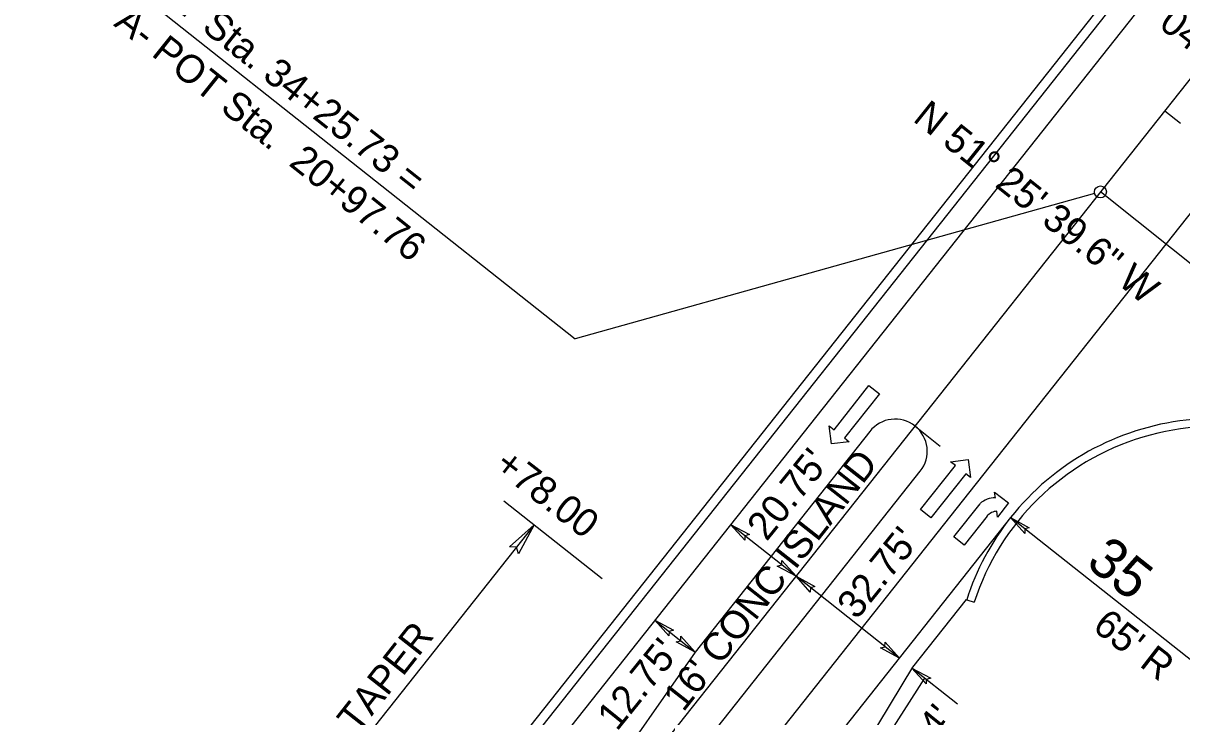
# Model space of a CAD drawing. Extents: x 1778969 to 1790720, y 807089 to 817794.
# Drawn here: x 1781916 to 1782204, y 813729.3 to 813901.8 of the extents above; entities that cross this region are included whole.
import ezdxf

# ---------------------------------------------------------------- set-up
doc = ezdxf.new("R2010")
doc.units = 0
for name, color, linetype in [('Prop Conc 2ft 6in Curb and Gutter', 7, 'Continuous'), ('Prop Conc 5in Monolithic Surface Mount Island', 7, 'Continuous'), ('Prop Conc Shoulder Berm Gutter', 7, 'Continuous'), ('Prop Dimension', 7, 'Continuous'), ('Prop Dimension Text', 7, 'Continuous'), ('Prop EOT', 7, 'Continuous'), ('Prop Guardrail', 7, 'Continuous'), ('Prop Horizontal Alignment', 7, 'Continuous'), ('Prop Horizontal Alignment Direction Label', 7, 'Continuous'), ('Prop Horizontal Alignment Station Label', 7, 'Continuous'), ('Prop Horizontal Alignment Tick Label', 7, 'Continuous'), ('Prop Horizontal Alignment Tick Large', 7, 'Continuous'), ('Prop Horizontal Alignment Tick Small', 7, 'Continuous'), ('Prop Lane Arrow CELL', 7, 'Continuous'), ('Prop Lane Lines', 7, 'Continuous'), ('Prop Paved Shoulder', 7, 'Continuous'), ('Prop Terminator CELL', 7, 'Continuous'), ('Scratch_Level_2', 7, 'Continuous'), ('Scratch_Level_7', 7, 'Continuous'), ('Scratch_Level_8', 7, 'Continuous')]:
    doc.layers.add(name, color=color, linetype=linetype)

msp = doc.modelspace()

# ---------------------------------------------------------------- linework, layer by layer
at = {"layer": 'Prop Conc 2ft 6in Curb and Gutter'}
msp.add_line((1782150.56, 813758.42), (1782152.46, 813757.81), dxfattribs=at)
for radius, start in [(63, 51.2517), (65, 141.6309)]:
    msp.add_arc((1782212.43, 813738.51), radius, start, 162.1578, dxfattribs=at)
at = {"layer": 'Prop Conc 5in Monolithic Surface Mount Island'}
for p, q in [((1782126.48, 813800.31), (1782083.03, 813745.43)), ((1782126.48, 813800.31), (1782083.03, 813745.43)), ((1781549.8, 813046.14), (1782139.02, 813790.38)), ((1781549.8, 813046.14), (1782139.02, 813790.38)), ((1782083.03, 813745.43), (1781968.29, 813581.17)), ((1782083.03, 813745.43), (1781968.29, 813581.17))]:
    msp.add_line(p, q, dxfattribs=at)
msp.add_arc((1782132.75, 813795.34), 8, 321.6309, 141.6309, dxfattribs=at)
msp.add_arc((1782132.75, 813795.34), 8, 321.6309, 141.6309, dxfattribs=at)
at = {"layer": 'Prop Conc Shoulder Berm Gutter'}
msp.add_line((1782463.39, 814255.53), (1782011.16, 813684.33), dxfattribs=at)
at = {"layer": 'Prop Dimension'}
for p, q in [((1782035.5, 813783.05), (1782059.91, 813763.73)), ((1782043.04, 813777.09), (1781918.89, 813620.28)), ((1782108.14, 813764.26), (1782091.87, 813777.14)), ((1782212.43, 813738.51), (1782161.47, 813778.86)), ((1782133.82, 813743.93), (1782108.14, 813764.26)), ((1782073.09, 813753.3), (1782083.03, 813745.43)), ((1782148.26, 813732.49), (1782136.95, 813741.45))]:
    msp.add_line(p, q, dxfattribs=at)
at = {"layer": 'Prop EOT'}
for p, q in [((1782467.83, 814252.01), (1781527.26, 813063.99)), ((1782161.47, 813778.86), (1782107.53, 813710.72))]:
    msp.add_line(p, q, dxfattribs=at)
msp.add_arc((1782212.43, 813738.51), 65, 51.2517, 141.6309, dxfattribs=at)
for points in [[(1781463.3, 813949.03), (1781464.17, 813947.59), (1781465.05, 813946.15), (1781465.92, 813944.71), (1781474.8, 813929.99), (1781483.67, 813915.26), (1781492.5, 813900.51), (1781500.58, 813887.01), (1781508.59, 813873.47), (1781516.69, 813859.98), (1781525.21, 813845.83), (1781533.74, 813831.69), (1781542.26, 813817.54), (1781551.3, 813802.52), (1781560.33, 813787.49), (1781569.37, 813772.46), (1781578.14, 813757.89), (1781587.14, 813743.46), (1781595.91, 813728.89), (1781604.33, 813714.9), (1781612.49, 813700.76), (1781620.9, 813686.76), (1781629.44, 813672.57), (1781637.98, 813658.38), (1781646.54, 813644.19), (1781655.1, 813630), (1781663.72, 813615.84), (1781672.26, 813601.63), (1781680.69, 813587.61), (1781689, 813573.52), (1781697.41, 813559.48), (1781705.95, 813545.23), (1781714.52, 813530.99), (1781723.07, 813516.73), (1781731.64, 813502.44), (1781740.12, 813488.1), (1781748.7, 813473.81), (1781757.55, 813459.07), (1781766.63, 813444.47), (1781775.52, 813429.74), (1781784.14, 813415.46), (1781792.67, 813401.11), (1781801.32, 813386.83), (1781809.96, 813372.55), (1781818.65, 813358.29), (1781827.3, 813344.02), (1781835.99, 813329.66), (1781844.67, 813315.3), (1781853.35, 813300.93), (1781861.54, 813287.37), (1781869.6, 813273.73), (1781877.8, 813260.18), (1781886.68, 813245.53), (1781895.77, 813231.01), (1781904.68, 813216.38), (1781913.11, 813202.51), (1781921.54, 813188.63), (1781929.97, 813174.75), (1781938.85, 813160.12), (1781947.7, 813145.46), (1781956.59, 813130.83), (1781964.95, 813117.07), (1781973.52, 813103.43), (1781982.19, 813089.85), (1781991.2, 813075.72), (1782000.27, 813061.63), (1782009.36, 813047.54), (1782018.57, 813033.28), (1782027.8, 813019.03), (1782037.07, 813004.8), (1782046.22, 812990.76), (1782055.4, 812976.74), (1782064.84, 812962.89), (1782074.16, 812949.23), (1782083.5, 812935.58), (1782092.82, 812921.91), (1782102.18, 812908.19), (1782111.54, 812894.47), (1782120.9, 812880.75), (1782130.3, 812866.98), (1782139.85, 812853.32), (1782149.42, 812839.67), (1782158.88, 812826.17), (1782168.45, 812812.74), (1782178.15, 812799.41), (1782187.7, 812786.29), (1782197.57, 812773.41), (1782207.08, 812760.26), (1782216.45, 812747.28), (1782225.83, 812734.3), (1782235.2, 812721.32)], [(1781718, 813799.07), (1781725.25, 813787.64), (1781732.32, 813776.09), (1781739.53, 813764.62), (1781748.41, 813750.49), (1781757.28, 813736.36), (1781766.17, 813722.23), (1781775.05, 813708.11), (1781784.04, 813694.06), (1781792.91, 813679.93), (1781801.78, 813665.79), (1781810.64, 813651.64), (1781819.51, 813637.51), (1781828.35, 813623.41), (1781837.2, 813609.31), (1781846.04, 813595.21), (1781854.91, 813581.09), (1781863.8, 813566.98), (1781872.77, 813552.92), (1781881.67, 813538.97), (1781890.62, 813525.06), (1781899.56, 813511.14), (1781909.02, 813496.43), (1781918.41, 813481.67), (1781927.98, 813467.03), (1781936.67, 813453.72), (1781945.44, 813440.46), (1781954.18, 813427.18), (1781963.4, 813413.19), (1781972.62, 813399.19), (1781981.85, 813385.2), (1781991.28, 813370.91), (1782000.79, 813356.66), (1782010.37, 813342.46), (1782019.44, 813329.02), (1782028.6, 813315.64), (1782037.78, 813302.29), (1782047.33, 813288.38), (1782056.88, 813274.48), (1782066.55, 813260.66), (1782076.08, 813247.05), (1782085.65, 813233.46), (1782095.22, 813219.88), (1782104.86, 813206.2), (1782114.49, 813192.52), (1782124.19, 813178.89), (1782133.79, 813165.38), (1782143.47, 813151.93), (1782153.2, 813138.53), (1782163.03, 813124.99), (1782172.87, 813111.45), (1782182.7, 813097.92), (1782192.49, 813084.44), (1782202.28, 813070.96), (1782212.1, 813057.5), (1782222.19, 813043.65), (1782232.6, 813030.04), (1782242.95, 813016.38), (1782253.03, 813003.08), (1782263.13, 812989.8), (1782273.21, 812976.5), (1782283.25, 812963.25), (1782293.24, 812949.97), (1782303.28, 812936.71), (1782313.15, 812923.68), (1782323.08, 812910.68), (1782333.22, 812897.85), (1782343.55, 812884.78), (1782353.98, 812871.79), (1782364.43, 812858.81), (1782374.92, 812845.79), (1782385.44, 812832.79), (1782395.93, 812819.76), (1782406.63, 812806.47), (1782417.16, 812793.03), (1782427.96, 812779.81), (1782438.52, 812766.89), (1782449.19, 812754.07), (1782459.83, 812741.21), (1782470.24, 812728.63), (1782480.58, 812715.98), (1782491.09, 812703.48), (1782501.82, 812690.7), (1782512.68, 812678.03), (1782523.5, 812665.33), (1782534.27, 812652.67), (1782545.05, 812640.01), (1782555.83, 812627.36), (1782566.67, 812614.64), (1782577.52, 812601.95), (1782588.45, 812589.31), (1782599.39, 812576.64), (1782610.53, 812564.14), (1782621.67, 812551.65), (1782632.74, 812539.22), (1782643.82, 812526.79), (1782655, 812514.46), (1782666.21, 812502.08), (1782677.45, 812489.72), (1782688.69, 812477.37), (1782699.92, 812465.03), (1782711.15, 812452.71), (1782722.41, 812440.4), (1782733.64, 812428.12), (1782744.98, 812415.94), (1782756.33, 812403.76), (1782767.99, 812391.23), (1782779.7, 812378.74), (1782791.5, 812366.34), (1782803.09, 812354.16), (1782814.85, 812342.15), (1782826.46, 812330), (1782838.01, 812317.9), (1782849.46, 812305.7), (1782861.02, 812293.59), (1782872.17, 812281.92), (1782883.35, 812270.25), (1782894.68, 812258.74), (1782906.41, 812246.83), (1782918.19, 812234.96), (1782929.97, 812223.1), (1782941.62, 812211.36), (1782953.24, 812199.57), (1782964.97, 812187.91), (1782968.29, 812184.62), (1782971.62, 812181.35), (1782974.95, 812178.08)]]:
    msp.add_open_spline(points, degree=3, dxfattribs=at)
at = {"layer": 'Prop Guardrail'}
msp.add_line((1782461.56, 814256.98), (1782009.33, 813685.78), dxfattribs=at)
at = {"layer": 'Prop Horizontal Alignment'}
for p, q in [((1782484.1, 814239.13), (1781543.53, 813051.11)), ((1782246.76, 813809.64), (1782183.81, 813859.84))]:
    msp.add_line(p, q, dxfattribs=at)
at = {"layer": 'Prop Horizontal Alignment Station Label'}
for p in [(1781926.47, 813923.69), (1782182.37, 813859.44)]:
    msp.add_line(p, (1782053.22, 813823.34), dxfattribs=at)
msp.add_circle((1782183.81, 813859.84), 1.5, dxfattribs=at)
at = {"layer": 'Prop Horizontal Alignment Tick Large'}
msp.add_line((1782137.72, 813801.62), (1782143.99, 813796.65), dxfattribs=at)
at = {"layer": 'Prop Horizontal Alignment Tick Small'}
msp.add_line((1782199.79, 813880.02), (1782203.71, 813876.91), dxfattribs=at)
at = {"layer": 'Prop Lane Arrow CELL'}
for p, q in [((1782117.58, 813800.71), (1782126.27, 813811.68)), ((1782126.27, 813811.68), (1782128.85, 813809.64)), ((1782128.85, 813809.64), (1782120.16, 813798.66)), ((1782116.95, 813797.18), (1782116.4, 813801.64)), ((1782116.4, 813801.64), (1782117.58, 813800.71)), ((1782121.34, 813797.73), (1782116.95, 813797.18)), ((1782120.16, 813798.66), (1782121.34, 813797.73)), ((1782139.06, 813780.84), (1782147.75, 813791.82)), ((1782146.57, 813792.75), (1782150.96, 813793.29)), ((1782147.75, 813791.82), (1782146.57, 813792.75)), ((1782150.96, 813793.29), (1782151.51, 813788.84)), ((1782150.33, 813789.77), (1782141.64, 813778.79)), ((1782151.51, 813788.84), (1782150.33, 813789.77)), ((1782157.69, 813783.73), (1782157.51, 813785.2)), ((1782157.51, 813785.2), (1782160.99, 813782.51)), ((1782160.99, 813782.51), (1782158.24, 813778.95)), ((1782141.64, 813778.79), (1782139.06, 813780.84)), ((1782147.35, 813774.05), (1782153.9, 813782.32)), ((1782158.24, 813778.95), (1782158.07, 813780.42)), ((1782155.62, 813779.18), (1782149.94, 813772)), ((1782149.94, 813772), (1782147.35, 813774.05))]:
    msp.add_line(p, q, dxfattribs=at)
for centre, radius, start, end in [((1782157.46, 813778.49), 5.25, 87.6432, 132.9549), ((1782158.18, 813777.16), 3.28, 91.9728, 141.6309)]:
    msp.add_arc(centre, radius, start, end, dxfattribs=at)
at = {"layer": 'Prop Lane Lines'}
msp.add_line((1782152.88, 813787.34), (1782077.29, 813691.86), dxfattribs=at)
at = {"layer": 'Prop Paved Shoulder'}
for p, q in [((1782150.46, 813758.5), (1782137.1, 813741.63)), ((1782137.1, 813741.63), (1782117.66, 813709.59))]:
    msp.add_line(p, q, dxfattribs=at)
at = {"layer": 'Prop Terminator CELL'}
for points in [[(1782036.92, 813771.6), (1782043.04, 813777.09), (1782039.11, 813769.81), (1782038.63, 813771.51)], [(1782095.38, 813773.22), (1782091.87, 813777.14), (1782096.53, 813774.62), (1782095.44, 813774.31)], [(1782164.98, 813774.94), (1782161.47, 813778.86), (1782166.13, 813776.34), (1782165.04, 813776.03)], [(1782104.63, 813768.17), (1782108.14, 813764.26), (1782103.48, 813766.77), (1782104.57, 813767.08)], [(1782111.65, 813760.34), (1782108.14, 813764.26), (1782112.8, 813761.74), (1782111.71, 813761.43)], [(1782076.54, 813749.42), (1782073.03, 813753.34), (1782077.69, 813750.83), (1782076.6, 813750.52)], [(1782079.52, 813749.34), (1782083.03, 813745.43), (1782078.37, 813747.94), (1782079.46, 813748.25)], [(1782130.31, 813747.85), (1782133.82, 813743.93), (1782129.16, 813746.44), (1782130.25, 813746.75)], [(1782140.46, 813737.53), (1782136.95, 813741.45), (1782141.61, 813738.93), (1782140.52, 813738.62)]]:
    msp.add_lwpolyline(points, close=True, dxfattribs=at)
at = {"layer": 'Scratch_Level_2'}
msp.add_line((1782270.85, 813936.34), (1782152.88, 813787.34), dxfattribs=at)
at = {"layer": 'Scratch_Level_7'}
msp.add_line((1782461.57, 814256.97), (1782009.34, 813685.77), dxfattribs=at)
at = {"layer": 'Scratch_Level_8'}
msp.add_line((1782140.09, 813738.96), (1782120.04, 813707.72), dxfattribs=at)

# ---------------------------------------------------------------- texts
at = {"layer": 'Prop Dimension Text'}
for s, rotation, p in [('+78.00', 322.2797, (1782032.74, 813791.01)), ("16' CONC ISLAND", 51.8142, (1782080.12, 813730.3)), ("20.75'", 51.0527, (1782100.84, 813772.76)), ("32.75'", 51.0527, (1782123.23, 813753.24)), ("65' R", 322.2797, (1782181.55, 813751.12)), ("200' LT. TURN LANE TAPER", 51.8028, (1781942.34, 813652.7)), ("12.75'", 51.0527, (1782063.61, 813725.53)), ("4'", 51.0527, (1782143.43, 813723.27))]:
    msp.add_text(s, height=7, rotation=rotation, dxfattribs=at).set_placement(p)
at = {"layer": 'Prop Horizontal Alignment Direction Label'}
for s, rotation, p in [('N 52%%d 04\' 47.7" W', 322.0799, (1782177.42, 813917.02)), ('N 51%%d 25\' 39.6" W', 321.4277, (1782136.92, 813877.64))]:
    msp.add_text(s, height=7, rotation=rotation, dxfattribs=at).set_placement(p)
at = {"layer": 'Prop Horizontal Alignment Station Label'}
for s, rotation, p in [('-Y- POT Sta. 34+25.73 =', 321.6309, (1781931.17, 813923.14)), ('-YLPA- POT Sta.  20+97.76', 321.4277, (1781922, 813914.32))]:
    msp.add_text(s, height=7, rotation=rotation, dxfattribs=at).set_placement(p)
at = {"layer": 'Prop Horizontal Alignment Tick Label'}
msp.add_text('35', height=10, rotation=321.6309, dxfattribs=at).set_placement((1782179.89, 813767.03))

doc.saveas('drawing.dxf')
